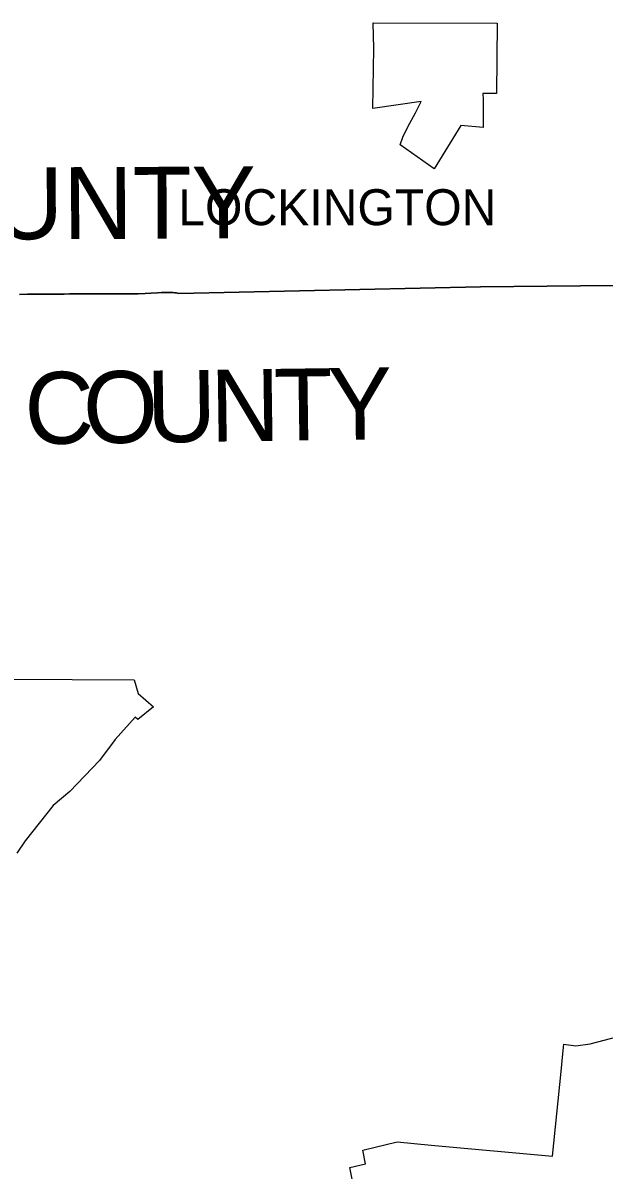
# Model space of a CAD drawing. Extents: x 0 to 34, y 0 to 22.
# Drawn here: x 5.0595 to 5.1893, y 17.5508 to 17.8072 of the extents above; entities that cross this region are included whole.
import ezdxf

# ---------------------------------------------------------------- set-up
doc = ezdxf.new("R2010")
doc.units = 0
for name, color, linetype in [('GM_X_Corporation', 7, 'Continuous'), ('GM_X_Corporation_Text', 7, 'Continuous'), ('GM_X_County', 7, 'Continuous'), ('GM_X_County_Text', 7, 'Continuous')]:
    doc.layers.add(name, color=color, linetype=linetype)

msp = doc.modelspace()

# ---------------------------------------------------------------- linework, layer by layer
at = {"layer": 'GM_X_Corporation'}
msp.add_lwpolyline([(5.162269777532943, 17.79146180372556), (5.16229140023, 17.79008749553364), (5.162309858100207, 17.78862775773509), (5.162313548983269, 17.78711053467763), (5.162315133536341, 17.786620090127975), (5.162311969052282, 17.785134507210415), (5.162296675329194, 17.783851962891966), (5.1573289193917, 17.784269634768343), (5.151394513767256, 17.774592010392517), (5.143787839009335, 17.780006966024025), (5.1443784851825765, 17.781690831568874), (5.145523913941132, 17.784040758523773), (5.147176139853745, 17.787160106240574), (5.148479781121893, 17.789703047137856), (5.137682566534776, 17.788070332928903), (5.137933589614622, 17.80150278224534), (5.137772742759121, 17.807236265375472), (5.165479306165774, 17.807157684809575), (5.1653258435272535, 17.791460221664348), (5.164756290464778, 17.791456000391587), (5.1643428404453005, 17.79145072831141), (5.163675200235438, 17.791442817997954), (5.163028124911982, 17.791451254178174)], close=True, dxfattribs=at)
for points in [[(5.042715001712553, 17.660584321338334), (5.084355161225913, 17.66037640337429), (5.085259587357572, 17.657342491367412), (5.088683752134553, 17.654357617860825), (5.085224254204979, 17.651485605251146), (5.084591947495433, 17.65202984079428), (5.080091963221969, 17.647032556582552), (5.076614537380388, 17.64235748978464), (5.070031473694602, 17.635426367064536), (5.06627665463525, 17.632268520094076), (5.060034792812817, 17.624336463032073), (5.058140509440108, 17.621624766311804)], [(5.134231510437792, 17.542816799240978), (5.132569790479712, 17.551319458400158), (5.136063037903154, 17.55217325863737), (5.135438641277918, 17.555167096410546), (5.1431434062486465, 17.55703554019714), (5.150734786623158, 17.556314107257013), (5.17781694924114, 17.553833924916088), (5.179722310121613, 17.57279207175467), (5.180116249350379, 17.576713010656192), (5.1803335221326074, 17.578873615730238), (5.183047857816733, 17.578499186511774), (5.1862257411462, 17.57901073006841), (5.192514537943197, 17.580640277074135)]]:
    msp.add_lwpolyline(points, dxfattribs=at)
at = {"layer": 'GM_X_County'}
for points in [[(5.228751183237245, 17.74889733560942), (5.161745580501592, 17.748234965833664), (5.094328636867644, 17.746706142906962), (5.094077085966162, 17.74678946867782), (5.093798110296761, 17.746873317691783), (5.093435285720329, 17.74692869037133), (5.093058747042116, 17.746956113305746), (5.092498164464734, 17.746960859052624), (5.092290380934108, 17.74696191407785), (5.0914524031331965, 17.746961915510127), (5.090505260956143, 17.746932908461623), (5.089559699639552, 17.74690179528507), (5.0880894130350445, 17.746838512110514), (5.086828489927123, 17.746777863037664), (5.0852506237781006, 17.74668874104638), (5.08388000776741, 17.74665868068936), (5.0804590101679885, 17.746640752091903), (5.07745251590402, 17.74665657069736), (5.075925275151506, 17.74665077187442), (5.07434635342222, 17.74663863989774), (5.073713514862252, 17.74663758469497), (5.07218469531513, 17.746643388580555), (5.069918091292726, 17.746633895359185), (5.068704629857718, 17.74662809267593), (5.066964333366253, 17.746627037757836), (5.065172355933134, 17.746626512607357), (5.064013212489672, 17.74661807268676), (5.063538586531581, 17.74661543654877), (5.06306448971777, 17.746614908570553), (5.0624327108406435, 17.746611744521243), (5.0605378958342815, 17.74658801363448), (5.058746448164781, 17.746552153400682)], [(5.058746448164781, 17.746552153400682), (5.0605378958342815, 17.74658801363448), (5.0624327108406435, 17.746611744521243), (5.06306448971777, 17.746614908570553), (5.063538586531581, 17.74661543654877), (5.064013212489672, 17.74661807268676), (5.065172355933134, 17.746626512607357), (5.066964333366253, 17.746627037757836), (5.068704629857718, 17.74662809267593), (5.069918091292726, 17.746633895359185), (5.07218469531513, 17.746643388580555), (5.073713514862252, 17.74663758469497), (5.07434635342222, 17.74663863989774), (5.075925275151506, 17.74665077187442), (5.07745251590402, 17.74665657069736), (5.0804590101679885, 17.746640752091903), (5.08388000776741, 17.74665868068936), (5.0852506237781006, 17.74668874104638), (5.086828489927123, 17.746777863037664), (5.0880894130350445, 17.746838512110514), (5.089559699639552, 17.74690179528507), (5.090505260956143, 17.746932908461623), (5.0914524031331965, 17.746961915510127), (5.092290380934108, 17.74696191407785), (5.092498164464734, 17.746960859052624), (5.093058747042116, 17.746956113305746), (5.093435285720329, 17.74692869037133), (5.093798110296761, 17.746873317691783), (5.094077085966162, 17.74678946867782), (5.094328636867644, 17.746706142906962), (5.161745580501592, 17.748234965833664), (5.228751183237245, 17.74889733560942)]]:
    msp.add_lwpolyline(points, dxfattribs=at)

# ---------------------------------------------------------------- texts
at = {"layer": 'GM_X_Corporation_Text'}
msp.add_text('LOCKINGTON', height=0.008037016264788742, rotation=1.0000000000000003e-05, dxfattribs=at).set_placement((5.094217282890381, 17.76201939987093))
at = {"layer": 'GM_X_County_Text'}
for s, height, rotation, p in [('SHELBY COUNTY', 0.016074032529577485, 0.22667000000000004, (4.929997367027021, 17.7583578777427)), ('C', 0.016074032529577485, 0.790408, (5.059987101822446, 17.713035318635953)), ('O', 0.016074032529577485, 0.7905760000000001, (5.0730701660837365, 17.71321581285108)), ('U', 0.016074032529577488, 0.7912969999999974, (5.087284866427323, 17.713411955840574)), ('N', 0.016074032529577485, 0.7905590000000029, (5.1014992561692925, 17.713608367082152)), ('T', 0.016074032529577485, 0.790626, (5.115713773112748, 17.713804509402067)), ('Y', 0.016074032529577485, 0.7905760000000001, (5.12773598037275, 17.713970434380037))]:
    msp.add_text(s, height=height, rotation=rotation, dxfattribs=at).set_placement(p)

doc.saveas('drawing.dxf')
